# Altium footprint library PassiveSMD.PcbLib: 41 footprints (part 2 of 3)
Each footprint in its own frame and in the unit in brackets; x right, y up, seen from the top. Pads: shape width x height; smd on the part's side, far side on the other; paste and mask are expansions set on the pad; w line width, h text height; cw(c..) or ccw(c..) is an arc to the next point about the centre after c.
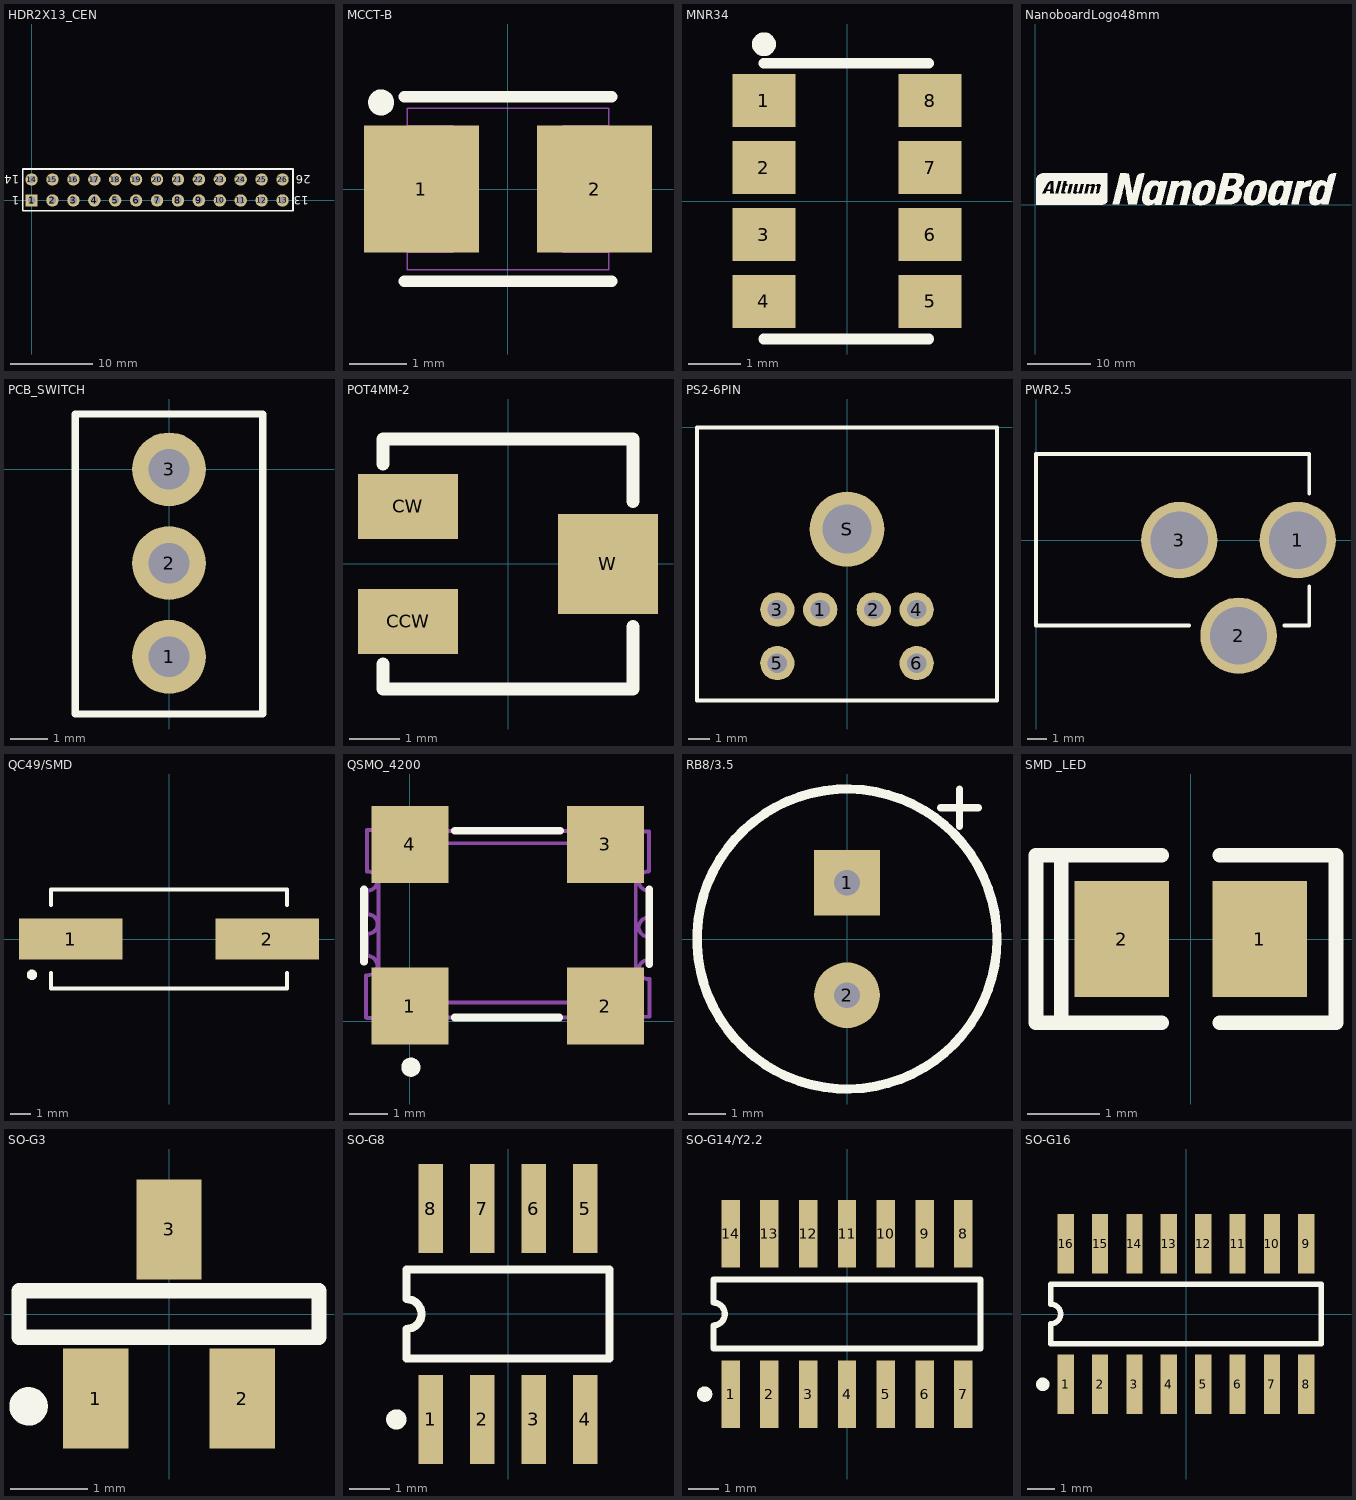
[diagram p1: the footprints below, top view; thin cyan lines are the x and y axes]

## HDR2X13_CEN [mm]
pads (26):
  rect 1.5x1.5 hole 0.9: 1(0,0)
  round 1.5 hole 0.9: 2(2.54,0) 3(5.08,0) 4(7.62,0) 5(10.16,0) 6(12.7,0) 7(15.24,0) 8(17.78,0) 9(20.32,0) 10(22.86,0) 11(25.4,0) 12(27.94,0) 13(30.48,0) 14(0,2.54) 15(2.54,2.54) 16(5.08,2.54) 17(7.62,2.54) 18(10.16,2.54) 19(12.7,2.54) 20(15.24,2.54) 21(17.78,2.54) 22(20.32,2.54) 23(22.86,2.54) 24(25.4,2.54) 25(27.94,2.54) 26(30.48,2.54)
Top Overlay:
  lines w0.2: -1.058,-1.27 31.75,-1.27 31.75,3.81 -1.058,3.81 -1.058,-1.27
  text "1" at -1.524,0.508 h1
  text "14" at -1.524,3.048 h1
  text "13" at 33.655,0.508 h1
  text "26" at 33.909,3.048 h1

## MCCT-B [mm]
pads (2):
  rect 2x2.2 smd: 1(-1.5,0) 2(1.5,0)
Top Overlay:
  circle w0.25: c-2.2,1.5 r0.1
  lines w0.2: -1.8,-1.6 1.8,-1.6 ; -1.8,1.6 1.8,1.6
Mechanical 15:
  lines w0.025: -1.75,-1.1 -0.95,-1.1 -0.95,1.1 -1.75,1.1 ; 1.75,-1.1 0.95,-1.1 0.95,1.1 1.75,1.1 ; -1.75,-1.4 1.75,-1.4 1.75,1.4 -1.75,1.4 -1.75,-1.4

## MNR34 [mm]
pads (8):
  rect 1.2x1 smd: 1(-1.575,1.905) 2(-1.575,0.635) 3(-1.575,-0.635) 4(-1.575,-1.905) 5(1.575,-1.905) 6(1.575,-0.635) 7(1.575,0.635) 8(1.575,1.905)
Top Overlay:
  circle w0.254: c-1.575,2.972 r0.1
  lines w0.2: -1.575,-2.616 1.549,-2.616 ; -1.575,2.616 1.549,2.616

## NanoboardLogo48mm [mm]
Top Overlay:
  drawing of 3446 lines, arcs and shapes, not listed

## PCB_SWITCH [mm]
pads (3):
  round 2 hole 1.1: 1(0,-5.08) 2(0,-2.54) 3(0,0)
Top Overlay:
  lines w0.2: -2.54,-6.63 2.54,-6.63 2.54,1.5 -2.54,1.5 -2.54,-6.63

## POT4MM-2 [mm]
pads (3):
  rect 2x1.3 smd: CCW(-2,-1.15) CW(-2,1.15)
  rect 2x2 smd: W(2,0)
Top Overlay:
  lines w0.254: -2.5,-2 -2.5,-2.5 2.5,-2.5 2.5,-1.25 ; -2.5,2 -2.5,2.5 2.5,2.5 2.5,1.25

## PS2-6PIN [mm]
pads (7):
  round 1.6 hole 0.9: 1(-1.25,-8.5) 2(1.25,-8.5) 3(-3.25,-8.5) 4(3.25,-8.5) 5(-3.25,-11) 6(3.25,-11)
  round 3.5 hole 2.29: S(0,-4.75)
Top Overlay:
  lines w0.2: -7,-12.75 7,-12.75 7,0 -7,0 -7,-12.75

## PWR2.5 [mm]
pads (3):
  round 4 hole 3: 1(13.7,0) 2(10.6,-5) 3(7.5,0)
Top Overlay:
  lines w0.2: 8,-4.475 0,-4.475 0,0.025 0,4.5 14.3,4.5 14.3,2.425 ; 13,-4.475 14.3,-4.475 14.3,-2.425

## QC49/SMD [mm]
pads (2):
  rect 5x2 smd: 1(-4.75,0) 2(4.75,0)
Top Overlay:
  circle w0.25: c-6.625,-1.73 r0.125
  lines w0.2: -5.7,-1.65 -5.7,-2.4 5.7,-2.4 5.7,-1.65 ; -5.7,1.65 -5.7,2.4 5.7,2.4 5.7,1.65

## QSMO_4200 [mm]
pads (4):
  rect 2x2 smd: 1(0,0.4) 2(5.08,0.4) 3(5.08,4.6) 4(0,4.6)
Top Overlay:
  circle w0.25: c0.025,-1.19 r0.125
  lines w0.2: -1.194,1.549 -1.194,3.429 ; 1.162,4.953 3.912,4.953 ; 1.168,0.102 3.886,0.102 ; 6.223,1.489 6.223,3.429
Mechanical 15:
  lines w0.1: -1.143,0.102 -1.143,1.194 ; -1.12,0.09 -0.27,0.09 -0.29,0.11 ; -1.12,3.9 -1.12,4.98 -0.26,4.98 ; -1.118,1.702 -1.118,2.286 ; -1.118,2.794 -1.118,3.378 ; -1.1,1.2 ccw(c-1.1,1.45) -1.1,1.7 ; -1.1,3.4 ccw(c-1.1,3.65) -1.1,3.9 ; -1.09,2.28 ccw(c-1.09,2.53) -1.09,2.78 ; -0.83,0.49 5.87,0.49 5.87,4.63 -0.82,4.63 -0.82,3.91 -0.82,0.51 ; -0.3,0.15 cw(c-0.05,0.15) 0.2,0.15 ; -0.23,4.91 ccw(c0.02,4.91) 0.27,4.91 ; 0.19,0.1 4.78,0.1 ; 0.25,4.95 4.87,4.95 ; 4.8,0.16 cw(c5.05,0.16) 5.3,0.16 ; 4.88,4.91 ccw(c5.13,4.91) 5.38,4.91 ; 5.29,0.12 6.23,0.12 6.23,1.1 ; 5.35,4.94 6.22,4.94 6.22,3.91 ; 6.198,1.62 6.198,2.184 ; 6.2,1.1 cw(c6.2,1.35) 6.2,1.6 ; 6.2,2.2 cw(c6.2,2.45) 6.2,2.7 ; 6.2,3.4 cw(c6.2,3.65) 6.2,3.9 ; 6.223,2.704 6.223,3.378

## RB8/3.5 [mil]
pads (2):
  rect 70x70 hole 27.56: 1(0,60)
  round 70 hole 27.56: 2(0,-60)
Top Overlay:
  circle w10: c0,0 r160
  lines w7.87: 100,140 140,140 ; 120,120 120,160

## SMD _LED [mm]
pads (2):
  rect 1.3x1.6 smd: 1(0.95,0) 2(-0.95,0)
Top Overlay:
  lines w0.2: -1.78,-1.15 -1.78,1.15 ; -0.4,-1.15 -2.13,-1.15 -2.13,1.15 -0.4,1.15 ; 0.4,-1.15 2,-1.15 2,1.15 0.4,1.15

## SO-G3 [mm]
pads (3):
  rect 0.85x1.3 smd: 1(-0.95,-1.1) 2(0.95,-1.1) 3(0,1.1)
Top Overlay:
  circle w0.25: c-1.825,-1.2 r0.125
  lines w0.2: -1.95,-0.3 1.95,-0.3 1.95,0.3 -1.95,0.3 -1.95,-0.3

## SO-G8 [mm]
pads (8):
  rect 0.6x2.2 smd: 1(-1.905,-2.6) 2(-0.635,-2.6) 3(0.635,-2.6) 4(1.905,-2.6) 5(1.905,2.6) 6(0.635,2.6) 7(-0.635,2.6) 8(-1.905,2.6)
Top Overlay:
  circle w0.25: c-2.755,-2.6 r0.125
  lines w0.2: -2.5,-1.1 2.5,-1.1 2.5,1.1 -2.5,1.1 -2.5,0.367 cw(c-2.5,0) -2.5,-0.367 -2.5,-1.1

## SO-G14/Y2.2 [mm]
pads (14):
  rect 0.6x2.2 smd: 1(-3.81,-2.625) 2(-2.54,-2.625) 3(-1.27,-2.625) 4(0,-2.625) 5(1.27,-2.625) 6(2.54,-2.625) 7(3.81,-2.625) 8(3.81,2.625) 9(2.54,2.625) 10(1.27,2.625) 11(0,2.625) 12(-1.27,2.625) 13(-2.54,2.625) 14(-3.81,2.625)
Top Overlay:
  circle w0.25: c-4.66,-2.625 r0.125
  lines w0.2: -4.375,-1.125 4.375,-1.125 4.375,1.125 -4.375,1.125 -4.375,0.375 cw(c-4.375,0) -4.375,-0.375 -4.375,-1.125

## SO-G16 [mm]
pads (16):
  rect 0.6x2.2 smd: 1(-4.445,-2.6) 2(-3.175,-2.6) 3(-1.905,-2.6) 4(-0.635,-2.6) 5(0.635,-2.6) 6(1.905,-2.6) 7(3.175,-2.6) 8(4.445,-2.6) 9(4.445,2.6) 10(3.175,2.6) 11(1.905,2.6) 12(0.635,2.6) 13(-0.635,2.6) 14(-1.905,2.6) 15(-3.175,2.6) 16(-4.445,2.6)
Top Overlay:
  circle w0.25: c-5.295,-2.6 r0.125
  lines w0.2: -5,-1.1 5,-1.1 5,1.1 -5,1.1 -5,0.367 cw(c-5,0) -5,-0.367 -5,-1.1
